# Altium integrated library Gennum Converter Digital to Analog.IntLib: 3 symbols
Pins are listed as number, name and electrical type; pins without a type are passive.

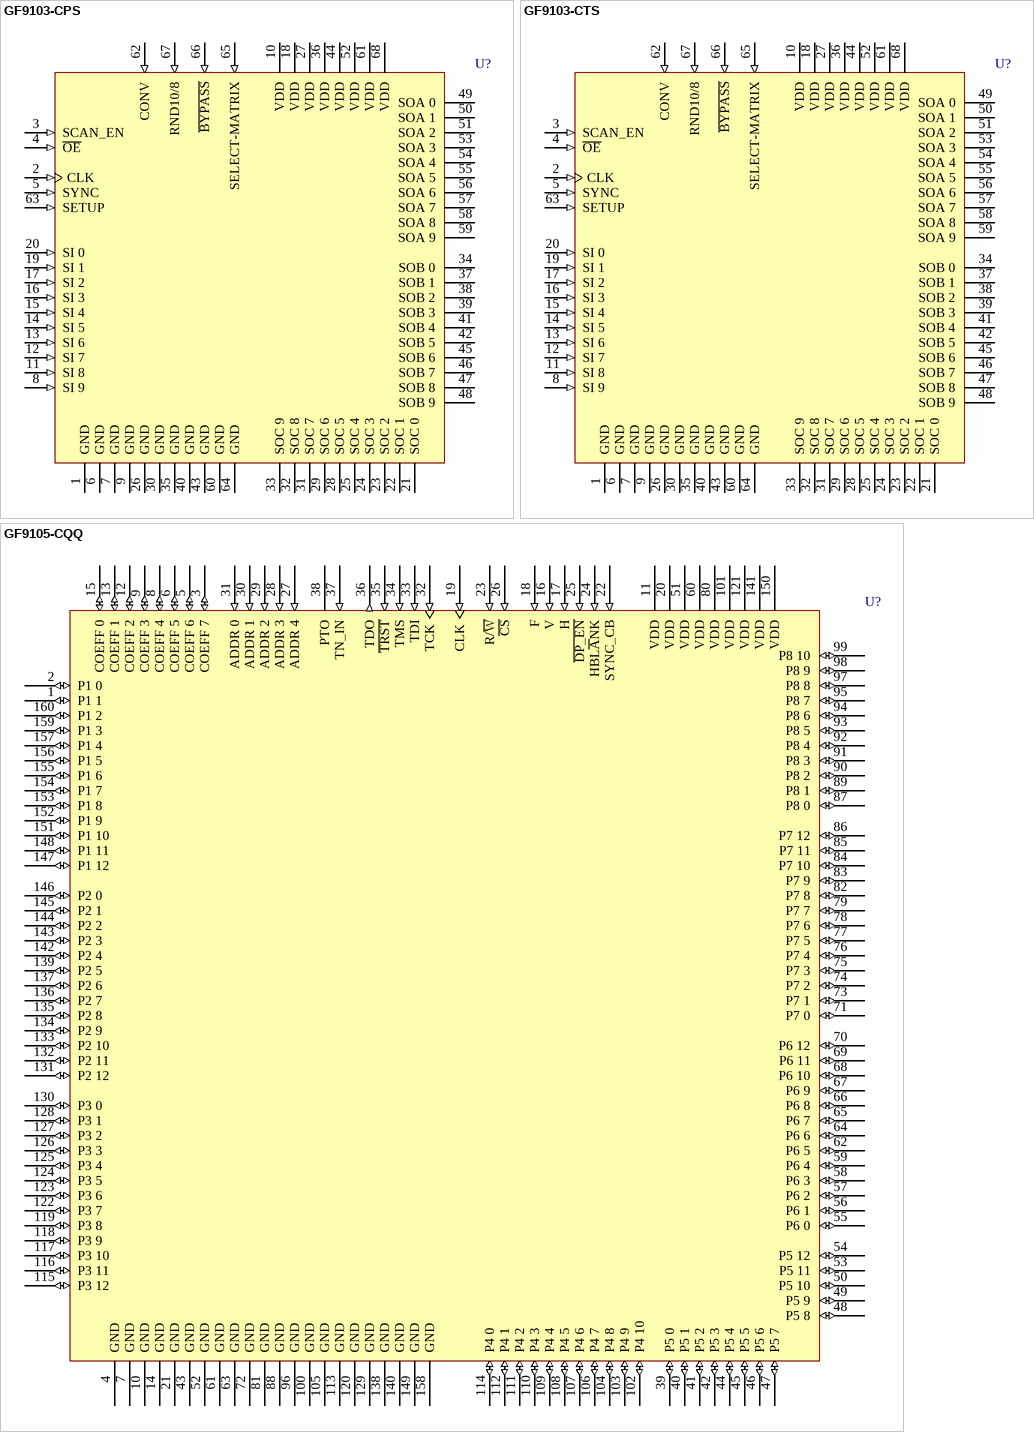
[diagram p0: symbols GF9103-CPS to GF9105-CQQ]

## GF9103-CPS
designator U?
Over-Sampling Color Space Converter
footprint PLCC68_N (Leaded Chip Carrier, 68-Leads, Body 24x24mm, Pitch 1.27mm, IPC Medium Density)
footprint PLCC68_L (Leaded Chip Carrier, 68-Leads, Body 24x24mm, Pitch 1.27mm, IPC High Density)
footprint PLCC68_M (Leaded Chip Carrier, 68-Leads, Body 24x24mm, Pitch 1.27mm, IPC Low Density)
3D model GF9103-PLCC68 (68-Pin Leaded Chip Carrier 1.27 mm Pitch)
pins: 1 GND (power), 2 CLK (in), 3 SCAN_EN (in), 4 ~{OE} (in), 5 SYNC (in), 6 GND (power), 7 GND (power), 8 SI 9 (in), 9 GND (power), 10 VDD (power), 11 SI 8 (in), 12 SI 7 (in), 13 SI 6 (in), 14 SI 5 (in), 15 SI 4 (in), 16 SI 3 (in), 17 SI 2 (in), 18 VDD (power), 19 SI 1 (in), 20 SI 0 (in), 21 SOC 0 (hiz), 22 SOC 1 (hiz), 23 SOC 2 (hiz), 24 SOC 3 (hiz), 25 SOC 4 (hiz), 26 GND (power), 27 VDD (power), 28 SOC 5 (hiz), 29 SOC 6 (hiz), 30 GND (power), 31 SOC 7 (hiz), 32 SOC 8 (hiz), 33 SOC 9 (hiz), 34 SOB 0 (hiz), 35 GND (power), 36 VDD (power), 37 SOB 1 (hiz), 38 SOB 2 (hiz), 39 SOB 3 (hiz), 40 GND (power), 41 SOB 4 (hiz), 42 SOB 5 (hiz), 43 GND (power), 44 VDD (power), 45 SOB 6 (hiz), 46 SOB 7 (hiz), 47 SOB 8 (hiz), 48 SOB 9 (hiz), 49 SOA 0 (hiz), 50 SOA 1 (hiz), 51 SOA 2 (hiz), 52 VDD (power), 53 SOA 3 (hiz), 54 SOA 4 (hiz), 55 SOA 5 (hiz), 56 SOA 6 (hiz), 57 SOA 7 (hiz), 58 SOA 8 (hiz), 59 SOA 9 (hiz), 60 GND (power), 61 VDD (power), 62 CONV (in), 63 SETUP (in), 64 GND (power), 65 SELECT-MATRIX (in), 66 ~{BYPASS} (in), 67 RND10/8 (in), 68 VDD (power)

## GF9103-CTS
designator U?
Over-Sampling Color Space Converter
footprint PLCC68T_N (Leaded Chip Carrier, 68-Leads, Body 24x24mm, Pitch 1.27mm, IPC Medium Density)
footprint PLCC68T_L (Leaded Chip Carrier, 68-Leads, Body 24x24mm, Pitch 1.27mm, IPC High Density)
footprint PLCC68T_M (Leaded Chip Carrier, 68-Leads, Body 24x24mm, Pitch 1.27mm, IPC Low Density)
3D model GF9103-PLCC68 (68-Pin Leaded Chip Carrier 1.27 mm Pitch)
pins: 1 GND (power), 2 CLK (in), 3 SCAN_EN (in), 4 ~{OE} (in), 5 SYNC (in), 6 GND (power), 7 GND (power), 8 SI 9 (in), 9 GND (power), 10 VDD (power), 11 SI 8 (in), 12 SI 7 (in), 13 SI 6 (in), 14 SI 5 (in), 15 SI 4 (in), 16 SI 3 (in), 17 SI 2 (in), 18 VDD (power), 19 SI 1 (in), 20 SI 0 (in), 21 SOC 0 (hiz), 22 SOC 1 (hiz), 23 SOC 2 (hiz), 24 SOC 3 (hiz), 25 SOC 4 (hiz), 26 GND (power), 27 VDD (power), 28 SOC 5 (hiz), 29 SOC 6 (hiz), 30 GND (power), 31 SOC 7 (hiz), 32 SOC 8 (hiz), 33 SOC 9 (hiz), 34 SOB 0 (hiz), 35 GND (power), 36 VDD (power), 37 SOB 1 (hiz), 38 SOB 2 (hiz), 39 SOB 3 (hiz), 40 GND (power), 41 SOB 4 (hiz), 42 SOB 5 (hiz), 43 GND (power), 44 VDD (power), 45 SOB 6 (hiz), 46 SOB 7 (hiz), 47 SOB 8 (hiz), 48 SOB 9 (hiz), 49 SOA 0 (hiz), 50 SOA 1 (hiz), 51 SOA 2 (hiz), 52 VDD (power), 53 SOA 3 (hiz), 54 SOA 4 (hiz), 55 SOA 5 (hiz), 56 SOA 6 (hiz), 57 SOA 7 (hiz), 58 SOA 8 (hiz), 59 SOA 9 (hiz), 60 GND (power), 61 VDD (power), 62 CONV (in), 63 SETUP (in), 64 GND (power), 65 SELECT-MATRIX (in), 66 ~{BYPASS} (in), 67 RND10/8 (in), 68 VDD (power)

## GF9105-CQQ
designator U?
Component Digital Transcoder; Note: Do not connect pin 38.
footprint MQFP160_N (QFP, 160-Leads, Body 28 x 28mm, Pitch 0.65mm, IPC Medium Density)
footprint MQFP160_L (QFP, 160-Leads, Body 28 x 28mm, Pitch 0.65mm, IPC High Density)
footprint MQFP160_M (QFP, 160-Leads, Body 28 x 28mm, Pitch 0.65mm, IPC Low Density)
3D model GF9105-MQFP160 (160-Pin Quad Flat Pack 0.65 mm Pitch)
pins: 1 P1 1 (io), 2 P1 0 (io), 3 COEFF 7 (io), 4 GND (power), 5 COEFF 6 (io), 6 COEFF 5 (io), 7 GND (power), 8 COEFF 4 (io), 9 COEFF 3 (io), 10 GND (power), 11 VDD (power), 12 COEFF 2 (io), 13 COEFF 1 (io), 14 GND (power), 15 COEFF 0 (io), 16 V (in), 17 H (in), 18 F (in), 19 CLK (in), 20 VDD (power), 21 GND (power), 22 SYNC_CB (in), 23 R/~{W} (in), 24 HBL~{A}NK (in), 25 ~{DP_EN} (in), 26 ~{CS} (in), 27 ADDR 4 (in), 28 ADDR 3 (in), 29 ADDR 2 (in), 30 ADDR 1 (in), 31 ADDR 0 (in), 32 TCK (in), 33 TDI (in), 34 TMS (in), 35 ~{TRST} (in), 36 TDO (out), 37 TN_IN (in), 38 PTO, 39 P5 0 (io), 40 P5 1 (io), 41 P5 2 (io), 42 P5 3 (io), 43 GND (power), 44 P5 4 (io), 45 P5 5 (io), 46 P5 6 (io), 47 P5 7 (io), 48 P5 8 (io), 49 P5 9 (io), 50 P5 10 (io), 51 VDD (power), 52 GND (power), 53 P5 11 (io), 54 P5 12 (io), 55 P6 0 (io), 56 P6 1 (io), 57 P6 2 (io), 58 P6 3 (io), 59 P6 4 (io), 60 VDD (power), 61 GND (power), 62 P6 5 (io), 63 GND (power), 64 P6 6 (io), 65 P6 7 (io), 66 P6 8 (io), 67 P6 9 (io), 68 P6 10 (io), 69 P6 11 (io), 70 P6 12 (io), 71 P7 0 (io), 72 GND (power), 73 P7 1 (io), 74 P7 2 (io), 75 P7 3 (io), 76 P7 4 (io), 77 P7 5 (io), 78 P7 6 (io), 79 P7 7 (io), 80 VDD (power), 81 GND (power), 82 P7 8 (io), 83 P7 9 (io), 84 P7 10 (io), 85 P7 11 (io), 86 P7 12 (io), 87 P8 0 (io), 88 GND (power), 89 P8 1 (io), 90 P8 2 (io), 91 P8 3 (io), 92 P8 4 (io), 93 P8 5 (io), 94 P8 6 (io), 95 P8 7 (io), 96 GND (power), 97 P8 8 (io), 98 P8 9 (io), 99 P8 10 (io), 100 GND (power), 101 VDD (power), 102 P4 10 (io), 103 P4 9 (io), 104 P4 8 (io), 105 GND (power), 106 P4 7 (io), 107 P4 6 (io), 108 P4 5 (io), 109 P4 4 (io), 110 P4 3 (io), 111 P4 2 (io), 112 P4 1 (io), 113 GND (power), 114 P4 0 (io), 115 P3 12 (io), 116 P3 11 (io), 117 P3 10 (io), 118 P3 9 (io), 119 P3 8 (io), 120 GND (power), 121 VDD (power), 122 P3 7 (io), 123 P3 6 (io), 124 P3 5 (io), 125 P3 4 (io), 126 P3 3 (io), 127 P3 2 (io), 128 P3 1 (io), 129 GND (power), 130 P3 0 (io), 131 P2 12 (io), 132 P2 11 (io), 133 P2 10 (io), 134 P2 9 (io), 135 P2 8 (io), 136 P2 7 (io), 137 P2 6 (io), 138 GND (power), 139 P2 5 (io), 140 GND (power), 141 VDD (power), 142 P2 4 (io), 143 P2 3 (io), 144 P2 2 (io), 145 P2 1 (io), 146 P2 0 (io), 147 P1 12 (io), 148 P1 11 (io), 149 GND (power), 150 VDD (power), 151 P1 10 (io), 152 P1 9 (io), 153 P1 8 (io), 154 P1 7 (io), 155 P1 6 (io), 156 P1 5 (io), 157 P1 4 (io), 158 GND (power), 159 P1 3 (io), 160 P1 2 (io)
